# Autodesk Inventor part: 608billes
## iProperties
Shininess: 64.0
Length Units: 11269
Angle Units: 11279
Time Units: 11290
Mass Units: 11283
Length Display Precision: 3
Angle Display Precision: 2
Compacted: True
Part Number: 608billes
Document SubType Name: Modeling
Created: 2004-09
Material: Par défaut
Density: 1 g/cm^3
Density: 0.0
Volumn: 0.0
Area: 0.0
PropertySet Name: Model Information
Control State: 0
Master: False
Checked Out: False
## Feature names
1. Révolution1 [Revolution]
